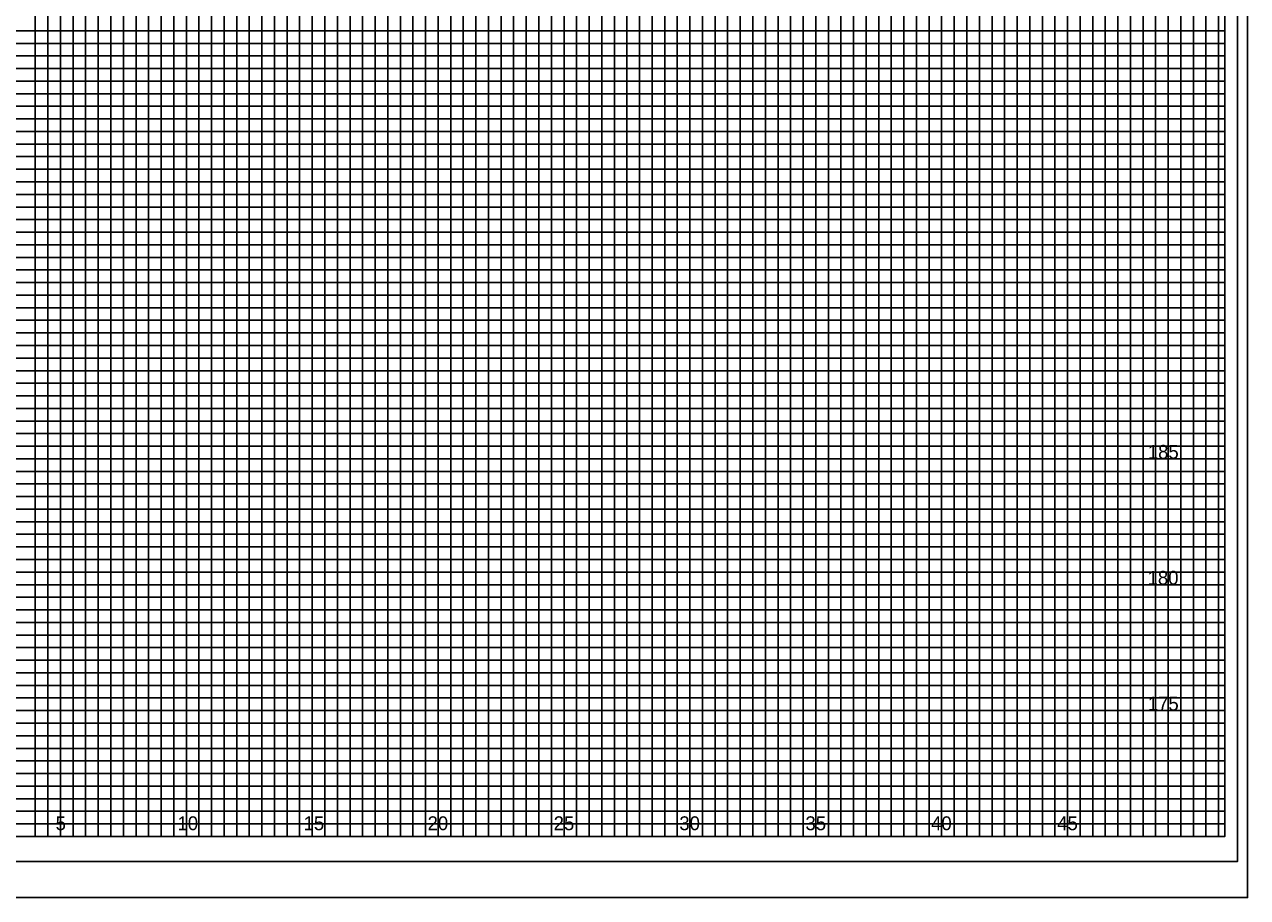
# Model space of a CAD drawing. Extents: x -4 to 103, y -2 to 280.
# Drawn here: x 54.82 to 103.4, y 210.05 to 244.73 of the extents above; entities that cross this region are included whole.
import ezdxf

# ---------------------------------------------------------------- set-up
doc = ezdxf.new("R2010")
doc.units = 0
for name, color, linetype in [('Exist XS Center Line Elevation Label', 7, 'Continuous'), ('Old_Level_63', 7, 'Continuous'), ('Prop XS Dump Level', 7, 'Continuous'), ('Prop XS Pvmt Edge Slope', 7, 'Continuous'), ('Prop XS SE Text', 7, 'Continuous'), ('Prop XS Subgrade Earthwork', 7, 'Continuous'), ('Sheet Cutting Line CELL', 7, 'Continuous'), ('Sheet Plot Border Inside CELL', 7, 'Continuous'), ('Sheet Plot Border Outside CELL', 7, 'Continuous')]:
    doc.layers.add(name, color=color, linetype=linetype)

msp = doc.modelspace()

# ---------------------------------------------------------------- linework, layer by layer
at = {"layer": 'Exist XS Center Line Elevation Label'}
for points in [[(56.25, 212.475), (56.25, 277.475)], [(58.75, 277.475), (58.75, 212.475), (61.25, 212.475), (61.25, 277.475)], [(63.75, 277.475), (63.75, 212.475), (66.25, 212.475), (66.25, 277.475)], [(68.75, 277.475), (68.75, 212.475), (71.25, 212.475), (71.25, 277.475)], [(73.75, 277.475), (73.75, 212.475), (76.25, 212.475), (76.25, 274.475)], [(88.75, 274.475), (88.75, 212.475), (91.25, 212.475), (91.25, 275.9)], [(93.75, 275.9), (93.75, 212.475), (96.25, 212.475), (96.25, 275.9)], [(98.75, 275.9), (98.75, 212.475), (101.25, 212.475), (101.25, 275.9)], [(78.75, 274.475), (78.75, 212.475), (81.25, 212.475), (81.25, 274.475)], [(83.75, 274.475), (83.75, 212.475), (86.25, 212.475), (86.25, 274.475)], [(0, 239.975), (102.5, 239.975), (102.5, 242.475), (0, 242.475)], [(0, 234.975), (102.5, 234.975), (102.5, 237.475), (0, 237.475)], [(0, 229.975), (102.5, 229.975), (102.5, 232.475), (0, 232.475)], [(0, 224.975), (102.5, 224.975), (102.5, 227.475), (0, 227.475)], [(0, 219.975), (102.5, 219.975), (102.5, 222.475), (0, 222.475)], [(0, 214.975), (102.5, 214.975), (102.5, 217.475), (0, 217.475)]]:
    msp.add_lwpolyline(points, dxfattribs=at)
at = {"layer": 'Old_Level_63'}
msp.add_lwpolyline([(102.5, 277.475), (0, 277.475), (0, 212.475), (102.5, 212.475)], close=True, dxfattribs=at)
at = {"layer": 'Prop XS Dump Level'}
for p, q in [((56.25, 212.475), (56.25, 277.475)), ((58.75, 212.475), (58.75, 277.475)), ((61.25, 212.475), (61.25, 277.475)), ((63.75, 212.475), (63.75, 277.475)), ((66.25, 212.475), (66.25, 277.475)), ((68.75, 212.475), (68.75, 277.475)), ((71.25, 212.475), (71.25, 277.475)), ((73.75, 212.475), (73.75, 277.475)), ((91.25, 212.475), (91.25, 275.9)), ((93.75, 212.475), (93.75, 275.9)), ((96.25, 212.475), (96.25, 275.9)), ((98.75, 212.475), (98.75, 275.9)), ((101.25, 212.475), (101.25, 275.9)), ((76.25, 212.475), (76.25, 274.475)), ((78.75, 212.475), (78.75, 274.475)), ((81.25, 212.475), (81.25, 274.475)), ((83.75, 212.475), (83.75, 274.475)), ((86.25, 212.475), (86.25, 274.475)), ((88.75, 212.475), (88.75, 274.475)), ((0, 242.475), (102.5, 242.475)), ((0, 239.975), (102.5, 239.975)), ((0, 237.475), (102.5, 237.475)), ((0, 234.975), (102.5, 234.975)), ((0, 232.475), (102.5, 232.475)), ((0, 229.975), (102.5, 229.975)), ((0, 227.475), (102.5, 227.475)), ((0, 224.975), (102.5, 224.975)), ((0, 222.475), (102.5, 222.475)), ((0, 219.975), (102.5, 219.975)), ((0, 217.475), (102.5, 217.475)), ((0, 214.975), (102.5, 214.975))]:
    msp.add_line(p, q, dxfattribs=at)
at = {"layer": 'Prop XS SE Text'}
for points in [[(54.75, 212.475), (55.25, 212.475), (55.25, 277.475)], [(55.75, 277.475), (55.75, 212.475), (56.75, 212.475), (56.75, 277.475)], [(57.25, 277.475), (57.25, 212.475), (57.75, 212.475), (57.75, 277.475)], [(58.25, 277.475), (58.25, 212.475), (59.25, 212.475), (59.25, 277.475)], [(59.75, 277.475), (59.75, 212.475), (60.25, 212.475), (60.25, 277.475)], [(60.75, 277.475), (60.75, 212.475), (61.75, 212.475), (61.75, 277.475)], [(62.25, 277.475), (62.25, 212.475), (62.75, 212.475), (62.75, 277.475)], [(63.25, 277.475), (63.25, 212.475), (64.25, 212.475), (64.25, 277.475)], [(64.75, 277.475), (64.75, 212.475), (65.25, 212.475), (65.25, 277.475)], [(65.75, 277.475), (65.75, 212.475), (66.75, 212.475), (66.75, 277.475)], [(67.25, 277.475), (67.25, 212.475), (67.75, 212.475), (67.75, 277.475)], [(68.25, 277.475), (68.25, 212.475), (69.25, 212.475), (69.25, 277.475)], [(69.75, 277.475), (69.75, 212.475), (70.25, 212.475), (70.25, 277.475)], [(70.75, 277.475), (70.75, 212.475), (71.75, 212.475), (71.75, 277.475)], [(72.25, 277.475), (72.25, 212.475), (72.75, 212.475), (72.75, 277.475)], [(73.25, 277.475), (73.25, 212.475), (74.25, 212.475), (74.25, 274.475)], [(89.75, 274.475), (89.75, 212.475), (90.25, 212.475), (90.25, 275.9)], [(90.75, 275.9), (90.75, 212.475), (91.75, 212.475), (91.75, 275.9)], [(92.25, 275.9), (92.25, 212.475), (92.75, 212.475), (92.75, 275.9)], [(93.25, 275.9), (93.25, 212.475), (94.25, 212.475), (94.25, 275.9)], [(94.75, 275.9), (94.75, 212.475), (95.25, 212.475), (95.25, 275.9)], [(95.75, 275.9), (95.75, 212.475), (96.75, 212.475), (96.75, 275.9)], [(97.25, 275.9), (97.25, 212.475), (97.75, 212.475), (97.75, 275.9)], [(98.25, 275.9), (98.25, 212.475), (99.25, 212.475), (99.25, 275.9)], [(99.75, 275.9), (99.75, 212.475), (100.25, 212.475), (100.25, 275.9)], [(100.25, 275.9), (100.75, 275.9), (100.75, 212.475), (101.75, 212.475), (101.75, 275.9), (102.25, 275.9), (102.25, 212.475)], [(74.75, 274.475), (74.75, 212.475), (75.25, 212.475), (75.25, 274.475)], [(75.75, 274.475), (75.75, 212.475), (76.75, 212.475), (76.75, 274.475)], [(77.25, 274.475), (77.25, 212.475), (77.75, 212.475), (77.75, 274.475)], [(78.25, 274.475), (78.25, 212.475), (79.25, 212.475), (79.25, 274.475)], [(79.75, 274.475), (79.75, 212.475), (80.25, 212.475), (80.25, 274.475)], [(80.75, 274.475), (80.75, 212.475), (81.75, 212.475), (81.75, 274.475)], [(82.25, 274.475), (82.25, 212.475), (82.75, 212.475), (82.75, 274.475)], [(83.25, 274.475), (83.25, 212.475), (84.25, 212.475), (84.25, 274.475)], [(84.75, 274.475), (84.75, 212.475), (85.25, 212.475), (85.25, 274.475)], [(85.75, 274.475), (85.75, 212.475), (86.75, 212.475), (86.75, 274.475)], [(87.25, 274.475), (87.25, 212.475), (87.75, 212.475), (87.75, 274.475)], [(88.25, 274.475), (88.25, 212.475), (89.25, 212.475), (89.25, 274.475)], [(0, 243.975), (102.5, 243.975), (102.5, 244.475), (0, 244.475)], [(0, 242.975), (102.5, 242.975), (102.5, 243.475), (0, 243.475)], [(0, 241.475), (102.5, 241.475), (102.5, 241.975), (0, 241.975)], [(0, 240.475), (102.5, 240.475), (102.5, 240.975), (0, 240.975)], [(0, 238.975), (102.5, 238.975), (102.5, 239.475), (0, 239.475)], [(0, 237.975), (102.5, 237.975), (102.5, 238.475), (0, 238.475)], [(0, 236.475), (102.5, 236.475), (102.5, 236.975), (0, 236.975)], [(0, 235.475), (102.5, 235.475), (102.5, 235.975), (0, 235.975)], [(0, 233.975), (102.5, 233.975), (102.5, 234.475), (0, 234.475)], [(0, 232.975), (102.5, 232.975), (102.5, 233.475), (0, 233.475)], [(0, 231.475), (102.5, 231.475), (102.5, 231.975), (0, 231.975)], [(0, 230.475), (102.5, 230.475), (102.5, 230.975), (0, 230.975)], [(0, 228.975), (102.5, 228.975), (102.5, 229.475), (0, 229.475)], [(0, 227.975), (102.5, 227.975), (102.5, 228.475), (0, 228.475)], [(0, 226.475), (102.5, 226.475), (102.5, 226.975), (0, 226.975)], [(0, 225.475), (102.5, 225.475), (102.5, 225.975), (0, 225.975)], [(0, 223.975), (102.5, 223.975), (102.5, 224.475), (0, 224.475)], [(0, 222.975), (102.5, 222.975), (102.5, 223.475), (0, 223.475)], [(0, 221.475), (102.5, 221.475), (102.5, 221.975), (0, 221.975)], [(0, 220.475), (102.5, 220.475), (102.5, 220.975), (0, 220.975)], [(0, 218.975), (102.5, 218.975), (102.5, 219.475), (0, 219.475)], [(0, 217.975), (102.5, 217.975), (102.5, 218.475), (0, 218.475)], [(0, 216.475), (102.5, 216.475), (102.5, 216.975), (0, 216.975)], [(0, 215.475), (102.5, 215.475), (102.5, 215.975), (0, 215.975)], [(0, 213.975), (102.5, 213.975), (102.5, 214.475), (0, 214.475)], [(0, 212.975), (102.5, 212.975), (102.5, 213.475), (0, 213.475)]]:
    msp.add_lwpolyline(points, dxfattribs=at)
at = {"layer": 'Sheet Cutting Line CELL'}
msp.add_line((-3.5, 210.05), (103.4, 210.05), dxfattribs=at)
at = {"layer": 'Sheet Plot Border Inside CELL'}
msp.add_lwpolyline([(103, 278.475), (-2.8, 278.475), (-2.8, 211.475), (103, 211.475)], close=True, dxfattribs=at)
at = {"layer": 'Sheet Plot Border Outside CELL'}
msp.add_lwpolyline([(103.4, 279.875), (-3.5, 279.875), (-3.5, 210.05), (103.4, 210.05)], close=True, dxfattribs=at)

# ---------------------------------------------------------------- texts
at = {"layer": 'Prop XS Pvmt Edge Slope'}
for s, p in [('5', (56.057, 212.725)), ('10', (60.897, 212.725)), ('15', (65.906, 212.725)), ('20', (70.831, 212.725)), ('25', (75.84, 212.725)), ('30', (80.831, 212.725)), ('35', (85.84, 212.725)), ('40', (90.831, 212.725)), ('45', (95.84, 212.725))]:
    msp.add_text(s, height=0.55, dxfattribs=at).set_placement(p)
at = {"layer": 'Prop XS Subgrade Earthwork'}
for s, p in [('185', (99.438, 227.475)), ('180', (99.43, 222.475)), ('175', (99.438, 217.475))]:
    msp.add_text(s, height=0.55, dxfattribs=at).set_placement(p)

doc.saveas('drawing.dxf')
